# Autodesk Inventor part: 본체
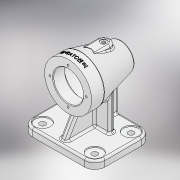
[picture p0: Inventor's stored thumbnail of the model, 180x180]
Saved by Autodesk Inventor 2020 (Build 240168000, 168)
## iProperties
Created: 2024-12
Part Number: 본체
Material: 알루미늄 6061
Document SubType Name: Modeling
Designer: 1강의실14
Mass: 739.149 g
Surface Area: 674.439 cm^2
Volume: 273.759 cm^3
Density: 2.7 g/cm^3
Appearance: 알루미늄 - 평지
Author: 1강의실14
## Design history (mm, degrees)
sketch "스케치1"
  geometry: L1 (37, 28)-(0, 28); L2 (0, 28)-(0, -56); L3 (0, -56)-(37, -56); L4 (37, -56)-(37, 28); L5 (23.5, 28)-(37, 28); L6 (37, 28)-(37, 8); L7 (37, 8)-(21, -56); L8 (21, -56)-(0, -56); L9 (23.5, 28)-(23.5, 10); L10 (23.5, 10)-(32.346, 10); L11 (32.346, 10)-(21.096, -35); L12 (21.096, -35)-(17.5, -35); L13 (17.5, -35)-(17.5, -45); L14 (17.5, -45)-(15.5, -45); L15 (15.5, -45)-(15.5, -48); L16 (15.5, -48)-(0, -48); 1 further point
  constraints: 32 end point, 6 perpendicular, 5 point on line, 4 parallel, 2 horizontal, 1 collinear, 1 vertical
  dimensions: "d0" = 84 distance of L1.end L2.end; "d1" = 74 diameter of L4 L2; "d2" = 56 distance of L2.end point (0, 0); "d14" = 18 distance of L5.start L9.end; "d15" = 20 distance of L1.start L6.end; "d16" = 42 diameter of L7.end L2; "d17" = 5 distance between parallel lines of L7 L11; "d18" = 31 diameter of L15 L2; "d19" = 35 diameter of L13 L2; "d20" = 3 distance of L14.end L15.end; "d21" = 10 distance of L12.end L13.end; "d22" = 45 distance from line of L12 L10.end; "d23" = 47 diameter of L9 L2
revolve "회전1" sketch "스케치1" stored, may be unused: angle "d24" = 90 deg
sketch "스케치2"
  geometry: L1 (-70, 43)-(-82, 43); L2 (-82, 43)-(-82, -46); L3 (-82, -46)-(-70, -46); L4 (-70, -46)-(-70, 43); L5 (-37, 28)-(37, 28) reference; 1 further point
  constraints: 8 end point, 2 parallel, 1 horizontal, 1 perpendicular
  dimensions: "d25" = 12 distance of L3.end L2.end; "d26" = 89 distance of L2.end L1.end; "d27" = 82 distance from line of L2 point (0, 0); "d28" = 15 distance between parallel lines of L5 L1
extrude "돌출1" join sketch "스케치2" stored distance "d29" = 114; taper "d30" = 0 deg
sketch "스케치3"
  geometry: L1 (29, 60)-(85, 60); L2 (85, 60)-(85, 52); L3 (85, 52)-(29, 52); L4 (29, 52)-(29, 60); L5 (0, 89)-(114, 89) reference; 2 further points
  constraints: 8 end point, 2 parallel, 1 horizontal, 1 midpoint, 1 perpendicular, 1 vertical alignment
  dimensions: "d31" = 8 distance of L1.end L2.end; "d32" = 29 distance between parallel lines of L1 L5; "d33" = 56 distance of L1.start L1.end
extrude "돌출2" join sketch "스케치3" stored distance "d34" = 114; taper "d35" = 0 deg; dims "d19" = 35
sketch "스케치4"
  geometry: L1 (-37, 28)-(-37, 8) reference; L2 (-37, 16.947)-(-70, 36); L3 (-70, 43)-(-70, -46) reference; L4 (-82, 43)-(-70, 43) reference; 1 further point
  constraints: 2 end point, 2 point on line
  dimensions: "d36" = 60 deg angle of L3 L2; "d37" = 7 distance from line of L4 L2.end
feature "리브1" sketch "스케치4" dims "d38" = 1, "d39" = 10, "d40" = 0, "d41" = 0, "d42" = 1, "d43" = 1
sketch "스케치5"
  geometry: L1 (0, 0)-(114, 0) reference; L2 (52, 0)-(62, 0); L3 (62, 0)-(62, -29); L4 (62, -29)-(52, -29); L5 (52, -29)-(52, 0); 3 further points
  constraints: 8 end point, 2 parallel, 1 horizontal, 1 midpoint, 1 perpendicular, 1 point on line, 1 vertical alignment
  dimensions: "d44" = 10 distance of L3.end L4.end; "d45" = 29 distance of L2.end L3.end
extrude "돌출3" join sketch "스케치5" stored distance "d46" = 114; taper "d47" = 0 deg; dims "d19" = 35
sketch "스케치6" dims "d48" = 57
  geometry: 3 further points
  constraints: 2 vertical alignment, 1 coincident, 2 other
hole "구멍1" sketch "스케치6" at (0, 28.5) diameter "d49" = 3.242; stored, may be unused: countersink angle "d53" = 90 deg, drill point angle "d55" = 120 deg; dims "d50" = 8, "d51" = 4, "d52" = 2, "d54" = 10
sketch "스케치7"
  geometry: L1 (0, 89)-(0, 0) reference; L2 (0, 89)-(114, 89) reference; 2 further points
  dimensions: "d60" = 16 distance from line of point (16, 73) L1; "d61" = 16 distance from line of point (16, 73) L2
hole "구멍2" sketch "스케치7" at (16, 73) diameter "d62" = 9; stored, may be unused: countersink angle "d66" = 90 deg, drill point angle "d68" = 120 deg; dims "d63" = 12, "d64" = 24, "d65" = 2, "d67" = 16
sketch "스케치8"
  geometry: L1 (33, 12.616)-(33, -38); L2 (33, -38)-(20.346, -38); L3 (20.346, -38)-(33, 12.616); L4 (21.096, -35)-(32.346, 10) reference; L5 (-82, -34.5)-(-82, -25.5) reference; L6 (-37, 28)-(37, 28) reference; 1 further point
  constraints: 6 end point, 2 collinear, 1 perpendicular, 1 vertical
  dimensions: "d75" = 115 distance between parallel lines of L5 L1; "d76" = 66 distance between parallel lines of L6 L2
extrude "돌출4" join sketch "스케치8" stored distance "d77" = 20; taper "d78" = 0 deg
sketch "스케치9"
  geometry: L1 (47, -66)-(-27, -66) reference; L2 (0, -35.928)-(0, 0) reference; L3 (20, 0)-(0, 0) reference; L4 (20, 0)-(20, -35.928) reference; C1 r 10 at (10, -10); 4 further points
  constraints: 1 centre point, 1 vertical alignment
  dimensions: "d79" = 20 diameter of C1; "d80" = 56 distance from line of L1 C1.centre
extrude "돌출5" cut sketch "스케치9" stored distance "d81" = 10.75; taper "d82" = 0 deg; dims "d19" = 35
sketch "스케치10"
  geometry: A1 r 10 centre (0, 0) between (10, 0) and (-10, 0) reference; 2 further points
  constraints: 1 coincident
hole "구멍3" sketch "스케치10" at (0, 0) diameter "d83" = 5.1881; stored, may be unused: countersink angle "d87" = 90 deg, drill point angle "d89" = 120 deg; dims "d84" = 12, "d85" = 10, "d86" = 1, "d88" = 16
node "작업 평면2"
sketch "스케치11"
  geometry: L1 (-37, 10)-(37, 10) reference; 2 further points
  constraints: 1 vertical alignment, 1 other
  dimensions: "d90" = 9 distance from line of L1 point (0, 1)
feature "엠보싱1" sketch "스케치11" dims "d0" = 84, "d1" = 74, "d2" = 56, "d14" = 18, "d15" = 20, "d16" = 42, "d17" = 5, "d18" = 31, "d19" = 35, "d20" = 3, "d21" = 10, "d22" = 45, "d23" = 47, "d25" = 12, "d26" = 89, "d27" = 82, "d28" = 15, "d91" = 0.5, "d92" = 0
chamfer "모따기1" distance "d93" = 1; stored, may be unused: second distance "d94" = 2, angle "d95" = 45 deg
fillet "모깎기1" dims "d96" = 16, "d97" = 5, "d98" = 0.3
fillet "모깎기2" dims "d99" = 3
fillet "모깎기3" dims "d100" = 3
fillet "모깎기4" dims "d101" = 3
node "솔리드1"
pattern_circular "원형 패턴1" dims angle "d57" = 360 deg
pattern_linear "직사각형 패턴1" dims "d71" = 57, "d74" = 82
feature "A9D066F2-1C7D-4E18-AEED-F7BC21143FA4" dims "d62" = 9, "d63" = 12, "d64" = 24, "d65" = 2, "d66" = 90 deg, "d67" = 16, "d68" = 120 deg
